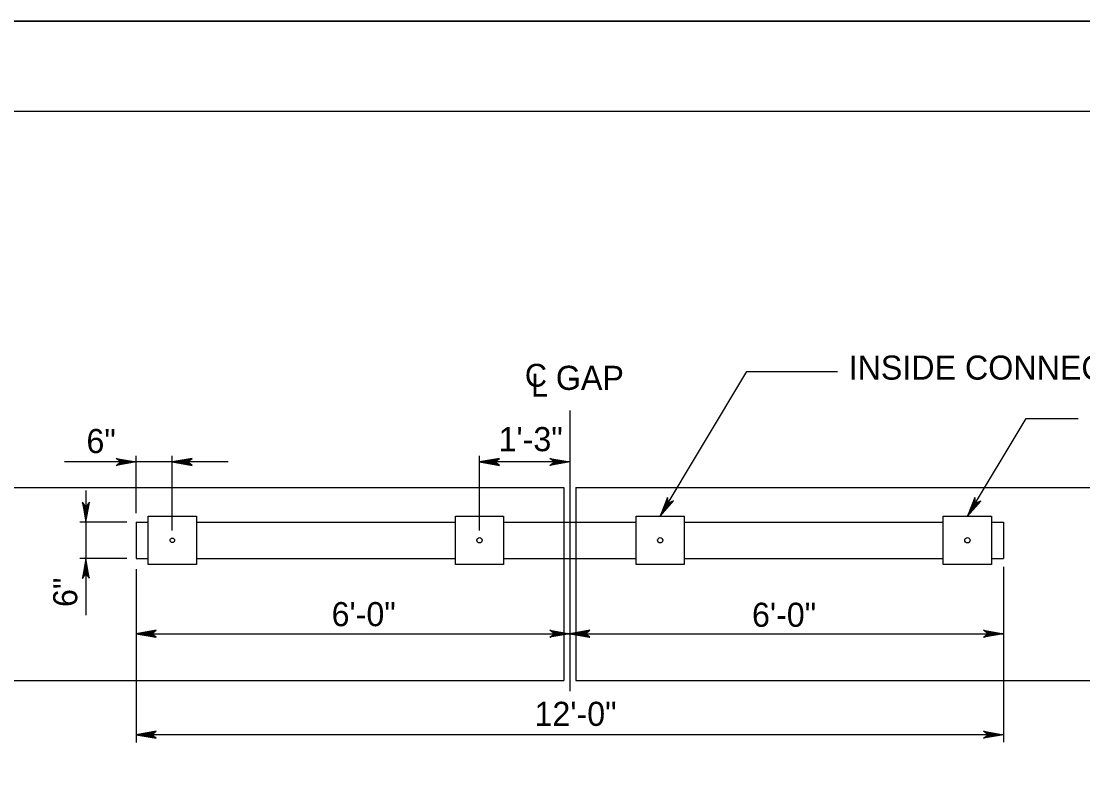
# Model space of a CAD drawing. Extents: x 499881 to 500993, y 499985 to 500645.
# Drawn here: x 500108.7 to 500285, y 500517.7 to 500645 of the extents above; entities that cross this region are included whole.
import ezdxf

# ---------------------------------------------------------------- set-up
doc = ezdxf.new("R2010")
doc.units = 0
for name, color, linetype in [('1', 7, 'Continuous'), ('2', 7, 'Continuous'), ('3', 7, 'Continuous'), ('41', 7, 'Continuous'), ('5', 7, 'Continuous')]:
    doc.layers.add(name, color=color, linetype=linetype)

msp = doc.modelspace()

# ---------------------------------------------------------------- linework, layer by layer
at = {"layer": '1'}
for p, q in [((499944.83, 500645), (500993, 500645)), ((500990, 500630), (500000, 500630))]:
    msp.add_line(p, q, dxfattribs=at)
at = {"layer": '2'}
for points in [[(500127.81, 500571.84), (500124.48, 500571.25), (500125.28, 500571.84), (500124.5, 500572.41), (500127.81, 500571.84), (500127.59, 500571.84), (500124.58, 500571.29), (500125.34, 500571.84), (500124.64, 500572.37), (500127.47, 500571.85), (500127.36, 500571.84), (500124.78, 500571.38), (500125.36, 500571.84), (500124.76, 500572.29), (500127.31, 500571.84), (500127.2, 500571.85), (500124.94, 500571.45), (500125.38, 500571.84), (500124.93, 500572.24), (500126.87, 500571.85), (500126.69, 500571.85), (500125.11, 500571.53), (500125.42, 500571.83), (500125.09, 500572.16), (500126.65, 500571.84), (500126.48, 500571.83), (500125.29, 500571.62), (500125.52, 500571.85), (500125.27, 500572.08), (500126.31, 500571.84), (500126.15, 500571.82), (500125.43, 500571.68), (500125.55, 500571.84), (500125.36, 500572.02), (500126.06, 500571.84), (500125.59, 500571.73), (500125.66, 500571.85), (500125.46, 500571.98), (500125.94, 500571.85), (500125.64, 500571.78), (500125.76, 500571.88), (500125.62, 500571.94), (500125.76, 500571.84), (500125.69, 500571.83)], [(500133.81, 500571.84), (500137.13, 500571.25), (500136.34, 500571.84), (500137.11, 500572.41), (500133.81, 500571.84), (500134.03, 500571.84), (500137.04, 500571.29), (500136.27, 500571.84), (500136.98, 500572.37), (500134.15, 500571.85), (500134.26, 500571.84), (500136.84, 500571.38), (500136.26, 500571.84), (500136.85, 500572.29), (500134.31, 500571.84), (500134.42, 500571.85), (500136.67, 500571.45), (500136.23, 500571.84), (500136.68, 500572.24), (500134.74, 500571.85), (500134.93, 500571.85), (500136.5, 500571.53), (500136.2, 500571.83), (500136.53, 500572.16), (500134.96, 500571.84), (500135.14, 500571.83), (500136.32, 500571.62), (500136.1, 500571.85), (500136.34, 500572.08), (500135.3, 500571.84), (500135.47, 500571.82), (500136.18, 500571.68), (500136.06, 500571.84), (500136.26, 500572.02), (500135.55, 500571.84), (500136.02, 500571.73), (500135.95, 500571.85), (500136.16, 500571.98), (500135.67, 500571.85), (500135.98, 500571.78), (500135.85, 500571.88), (500136, 500571.94), (500135.85, 500571.84), (500135.93, 500571.83)], [(500184.81, 500571.84), (500188.13, 500571.25), (500187.34, 500571.84), (500188.11, 500572.41), (500184.81, 500571.84), (500185.03, 500571.84), (500188.04, 500571.29), (500187.27, 500571.84), (500187.98, 500572.37), (500185.15, 500571.85), (500185.26, 500571.84), (500187.84, 500571.38), (500187.26, 500571.84), (500187.85, 500572.29), (500185.31, 500571.84), (500185.42, 500571.85), (500187.67, 500571.45), (500187.23, 500571.84), (500187.68, 500572.24), (500185.74, 500571.85), (500185.93, 500571.85), (500187.5, 500571.53), (500187.2, 500571.83), (500187.53, 500572.16), (500185.96, 500571.84), (500186.14, 500571.83), (500187.32, 500571.62), (500187.1, 500571.85), (500187.34, 500572.08), (500186.3, 500571.84), (500186.47, 500571.82), (500187.18, 500571.68), (500187.06, 500571.84), (500187.26, 500572.02), (500186.55, 500571.84), (500187.02, 500571.73), (500186.95, 500571.85), (500187.16, 500571.98), (500186.67, 500571.85), (500186.98, 500571.78), (500186.85, 500571.88), (500187, 500571.94), (500186.85, 500571.84), (500186.93, 500571.83)], [(500199.81, 500571.84), (500196.48, 500571.25), (500197.28, 500571.84), (500196.5, 500572.41), (500199.81, 500571.84), (500199.58, 500571.84), (500196.57, 500571.29), (500197.34, 500571.84), (500196.63, 500572.37), (500199.47, 500571.85), (500199.35, 500571.84), (500196.78, 500571.38), (500197.35, 500571.84), (500196.76, 500572.29), (500199.3, 500571.84), (500199.19, 500571.85), (500196.94, 500571.45), (500197.38, 500571.84), (500196.93, 500572.24), (500198.87, 500571.85), (500198.69, 500571.85), (500197.11, 500571.53), (500197.41, 500571.83), (500197.08, 500572.16), (500198.65, 500571.84), (500198.47, 500571.83), (500197.29, 500571.62), (500197.52, 500571.85), (500197.27, 500572.08), (500198.31, 500571.84), (500198.14, 500571.82), (500197.43, 500571.68), (500197.55, 500571.84), (500197.35, 500572.02), (500198.06, 500571.84), (500197.59, 500571.73), (500197.66, 500571.85), (500197.46, 500571.98), (500197.94, 500571.85), (500197.64, 500571.78), (500197.76, 500571.88), (500197.62, 500571.94), (500197.76, 500571.84), (500197.69, 500571.83)], [(500214.81, 500562.83), (500217.04, 500565.36), (500216.12, 500564.99), (500216.04, 500565.95), (500214.81, 500562.83), (500214.92, 500563.02), (500216.95, 500565.3), (500216.09, 500564.94), (500216, 500565.81), (500214.97, 500563.13), (500215.04, 500563.21), (500216.78, 500565.18), (500216.08, 500564.93), (500216, 500565.67), (500215.07, 500563.26), (500215.11, 500563.36), (500216.63, 500565.07), (500216.07, 500564.9), (500215.96, 500565.49), (500215.28, 500563.63), (500215.38, 500563.79), (500216.47, 500564.97), (500216.06, 500564.87), (500215.95, 500565.32), (500215.41, 500563.81), (500215.51, 500563.96), (500216.3, 500564.87), (500215.99, 500564.79), (500215.92, 500565.12), (500215.59, 500564.11), (500215.69, 500564.24), (500216.17, 500564.78), (500215.98, 500564.76), (500215.93, 500565.02), (500215.72, 500564.32), (500216.05, 500564.66), (500215.91, 500564.67), (500215.91, 500564.91), (500215.76, 500564.43), (500215.99, 500564.65), (500215.84, 500564.59), (500215.86, 500564.75), (500215.86, 500564.58), (500215.92, 500564.63)], [(500265.81, 500562.83), (500268.06, 500565.35), (500267.14, 500564.98), (500267.06, 500565.95), (500265.81, 500562.83), (500265.92, 500563.02), (500267.97, 500565.29), (500267.1, 500564.93), (500267.02, 500565.81), (500265.97, 500563.13), (500266.04, 500563.21), (500267.79, 500565.16), (500267.09, 500564.92), (500267.02, 500565.66), (500266.07, 500563.26), (500266.11, 500563.36), (500267.65, 500565.06), (500267.08, 500564.89), (500266.97, 500565.49), (500266.28, 500563.63), (500266.38, 500563.79), (500267.49, 500564.96), (500267.07, 500564.86), (500266.97, 500565.31), (500266.41, 500563.81), (500266.52, 500563.96), (500267.31, 500564.86), (500267, 500564.79), (500266.93, 500565.12), (500266.59, 500564.1), (500266.69, 500564.23), (500267.19, 500564.77), (500266.99, 500564.75), (500266.94, 500565.01), (500266.73, 500564.32), (500267.06, 500564.65), (500266.92, 500564.66), (500266.92, 500564.9), (500266.77, 500564.42), (500267, 500564.64), (500266.85, 500564.59), (500266.87, 500564.74), (500266.88, 500564.57), (500266.93, 500564.63)], [(500119.47, 500561.83), (500120.05, 500565.15), (500119.47, 500564.36), (500118.89, 500565.14), (500119.47, 500561.83), (500119.46, 500562.05), (500120.01, 500565.06), (500119.46, 500564.3), (500118.93, 500565), (500119.45, 500562.17), (500119.47, 500562.28), (500119.92, 500564.86), (500119.46, 500564.28), (500119.01, 500564.88), (500119.47, 500562.33), (500119.45, 500562.44), (500119.86, 500564.7), (500119.47, 500564.26), (500119.06, 500564.71), (500119.45, 500562.76), (500119.45, 500562.95), (500119.77, 500564.53), (500119.47, 500564.22), (500119.14, 500564.55), (500119.47, 500562.98), (500119.48, 500563.16), (500119.68, 500564.35), (500119.45, 500564.12), (500119.22, 500564.37), (500119.47, 500563.32), (500119.48, 500563.49), (500119.62, 500564.2), (500119.46, 500564.09), (500119.28, 500564.28), (500119.47, 500563.58), (500119.58, 500564.04), (500119.45, 500563.98), (500119.32, 500564.18), (500119.45, 500563.7), (500119.53, 500564), (500119.42, 500563.87), (500119.36, 500564.02), (500119.46, 500563.87), (500119.47, 500563.95)], [(500119.47, 500555.83), (500118.88, 500552.51), (500119.47, 500553.3), (500120.04, 500552.52), (500119.47, 500555.83), (500119.47, 500555.61), (500118.92, 500552.6), (500119.47, 500553.36), (500120, 500552.66), (500119.48, 500555.49), (500119.47, 500555.38), (500119.01, 500552.8), (500119.47, 500553.38), (500119.92, 500552.78), (500119.47, 500555.33), (500119.48, 500555.22), (500119.08, 500552.96), (500119.47, 500553.4), (500119.87, 500552.96), (500119.48, 500554.9), (500119.48, 500554.71), (500119.16, 500553.13), (500119.46, 500553.44), (500119.79, 500553.11), (500119.47, 500554.68), (500119.46, 500554.5), (500119.25, 500553.31), (500119.48, 500553.54), (500119.71, 500553.29), (500119.47, 500554.34), (500119.45, 500554.17), (500119.31, 500553.46), (500119.47, 500553.57), (500119.65, 500553.38), (500119.47, 500554.08), (500119.36, 500553.62), (500119.48, 500553.68), (500119.61, 500553.48), (500119.48, 500553.97), (500119.41, 500553.66), (500119.51, 500553.79), (500119.57, 500553.64), (500119.47, 500553.79), (500119.46, 500553.71)], [(500127.81, 500543.31), (500131.13, 500542.72), (500130.34, 500543.31), (500131.11, 500543.89), (500127.81, 500543.31), (500128.03, 500543.32), (500131.04, 500542.77), (500130.27, 500543.32), (500130.98, 500543.85), (500128.15, 500543.33), (500128.26, 500543.31), (500130.84, 500542.85), (500130.26, 500543.32), (500130.85, 500543.77), (500128.31, 500543.31), (500128.42, 500543.33), (500130.67, 500542.92), (500130.23, 500543.31), (500130.68, 500543.72), (500128.74, 500543.33), (500128.93, 500543.33), (500130.5, 500543.01), (500130.2, 500543.3), (500130.53, 500543.63), (500128.96, 500543.31), (500129.14, 500543.3), (500130.32, 500543.1), (500130.1, 500543.33), (500130.34, 500543.56), (500129.3, 500543.31), (500129.47, 500543.3), (500130.18, 500543.16), (500130.06, 500543.32), (500130.26, 500543.5), (500129.55, 500543.31), (500130.02, 500543.2), (500129.95, 500543.33), (500130.16, 500543.46), (500129.67, 500543.33), (500129.98, 500543.25), (500129.85, 500543.35), (500130, 500543.41), (500129.85, 500543.32), (500129.93, 500543.3)], [(500199.8, 500543.31), (500196.47, 500542.72), (500197.27, 500543.31), (500196.49, 500543.89), (500199.8, 500543.31), (500199.58, 500543.32), (500196.57, 500542.77), (500197.33, 500543.32), (500196.62, 500543.85), (500199.46, 500543.33), (500199.35, 500543.31), (500196.77, 500542.85), (500197.35, 500543.32), (500196.75, 500543.77), (500199.3, 500543.31), (500199.18, 500543.33), (500196.93, 500542.92), (500197.37, 500543.31), (500196.92, 500543.72), (500198.86, 500543.33), (500198.68, 500543.33), (500197.1, 500543.01), (500197.4, 500543.3), (500197.07, 500543.63), (500198.64, 500543.31), (500198.46, 500543.3), (500197.28, 500543.1), (500197.51, 500543.33), (500197.26, 500543.56), (500198.3, 500543.31), (500198.13, 500543.3), (500197.42, 500543.16), (500197.54, 500543.32), (500197.35, 500543.5), (500198.05, 500543.31), (500197.58, 500543.2), (500197.65, 500543.33), (500197.45, 500543.46), (500197.93, 500543.33), (500197.63, 500543.25), (500197.75, 500543.35), (500197.61, 500543.41), (500197.75, 500543.32), (500197.68, 500543.3)], [(500199.81, 500543.31), (500203.13, 500542.72), (500202.34, 500543.31), (500203.11, 500543.89), (500199.81, 500543.31), (500200.03, 500543.32), (500203.04, 500542.77), (500202.27, 500543.32), (500202.98, 500543.85), (500200.15, 500543.33), (500200.26, 500543.31), (500202.84, 500542.85), (500202.26, 500543.32), (500202.85, 500543.77), (500200.31, 500543.31), (500200.42, 500543.33), (500202.67, 500542.92), (500202.23, 500543.31), (500202.68, 500543.72), (500200.74, 500543.33), (500200.93, 500543.33), (500202.5, 500543.01), (500202.2, 500543.3), (500202.53, 500543.63), (500200.96, 500543.31), (500201.14, 500543.3), (500202.32, 500543.1), (500202.1, 500543.33), (500202.34, 500543.56), (500201.3, 500543.31), (500201.47, 500543.3), (500202.18, 500543.16), (500202.06, 500543.32), (500202.26, 500543.5), (500201.55, 500543.31), (500202.02, 500543.2), (500201.95, 500543.33), (500202.16, 500543.46), (500201.67, 500543.33), (500201.98, 500543.25), (500201.85, 500543.35), (500202, 500543.41), (500201.85, 500543.32), (500201.93, 500543.3)], [(500271.81, 500543.31), (500268.48, 500542.72), (500269.28, 500543.31), (500268.5, 500543.89), (500271.81, 500543.31), (500271.59, 500543.32), (500268.58, 500542.77), (500269.34, 500543.32), (500268.63, 500543.85), (500271.47, 500543.33), (500271.36, 500543.31), (500268.78, 500542.85), (500269.36, 500543.32), (500268.76, 500543.77), (500271.3, 500543.31), (500271.19, 500543.33), (500268.94, 500542.92), (500269.38, 500543.31), (500268.93, 500543.72), (500270.87, 500543.33), (500270.69, 500543.33), (500269.11, 500543.01), (500269.41, 500543.3), (500269.08, 500543.63), (500270.65, 500543.31), (500270.47, 500543.3), (500269.29, 500543.1), (500269.52, 500543.33), (500269.27, 500543.56), (500270.31, 500543.31), (500270.14, 500543.3), (500269.43, 500543.16), (500269.55, 500543.32), (500269.35, 500543.5), (500270.06, 500543.31), (500269.59, 500543.2), (500269.66, 500543.33), (500269.46, 500543.46), (500269.94, 500543.33), (500269.64, 500543.25), (500269.76, 500543.35), (500269.62, 500543.41), (500269.76, 500543.32), (500269.69, 500543.3)], [(500127.81, 500526.56), (500131.13, 500525.97), (500130.34, 500526.56), (500131.11, 500527.14), (500127.81, 500526.56), (500128.03, 500526.56), (500131.04, 500526.01), (500130.27, 500526.56), (500130.98, 500527.09), (500128.15, 500526.57), (500128.26, 500526.56), (500130.84, 500526.1), (500130.26, 500526.56), (500130.85, 500527.01), (500128.31, 500526.56), (500128.42, 500526.57), (500130.67, 500526.17), (500130.23, 500526.56), (500130.68, 500526.96), (500128.74, 500526.57), (500128.93, 500526.57), (500130.5, 500526.25), (500130.2, 500526.55), (500130.53, 500526.88), (500128.96, 500526.56), (500129.14, 500526.55), (500130.32, 500526.34), (500130.1, 500526.57), (500130.34, 500526.8), (500129.3, 500526.56), (500129.47, 500526.54), (500130.18, 500526.4), (500130.06, 500526.56), (500130.26, 500526.74), (500129.55, 500526.56), (500130.02, 500526.45), (500129.95, 500526.57), (500130.16, 500526.7), (500129.67, 500526.57), (500129.98, 500526.5), (500129.85, 500526.6), (500130, 500526.66), (500129.85, 500526.56), (500129.93, 500526.55)], [(500271.81, 500526.56), (500268.48, 500525.97), (500269.28, 500526.56), (500268.5, 500527.14), (500271.81, 500526.56), (500271.58, 500526.56), (500268.57, 500526.01), (500269.34, 500526.56), (500268.63, 500527.09), (500271.46, 500526.57), (500271.35, 500526.56), (500268.78, 500526.1), (500269.35, 500526.56), (500268.76, 500527.01), (500271.3, 500526.56), (500271.19, 500526.57), (500268.94, 500526.17), (500269.38, 500526.56), (500268.93, 500526.96), (500270.87, 500526.57), (500270.68, 500526.57), (500269.11, 500526.25), (500269.41, 500526.55), (500269.08, 500526.88), (500270.65, 500526.56), (500270.47, 500526.55), (500269.29, 500526.34), (500269.52, 500526.57), (500269.27, 500526.8), (500270.31, 500526.56), (500270.14, 500526.54), (500269.43, 500526.4), (500269.55, 500526.56), (500269.35, 500526.74), (500270.06, 500526.56), (500269.59, 500526.45), (500269.66, 500526.57), (500269.46, 500526.7), (500269.94, 500526.57), (500269.63, 500526.5), (500269.76, 500526.6), (500269.62, 500526.66), (500269.76, 500526.56), (500269.69, 500526.55)]]:
    msp.add_lwpolyline(points, dxfattribs=at)
at = {"layer": '3'}
for p, q in [((500214.81, 500562.83), (500229.22, 500586.85)), ((500229.22, 500586.85), (500244.25, 500586.85)), ((500199.81, 500580.38), (500199.81, 500533.81)), ((500265.81, 500562.83), (500275.54, 500579.06)), ((500275.54, 500579.06), (500284.21, 500579.06)), ((500127.81, 500563.35), (500127.81, 500572.85)), ((500133.81, 500560.43), (500133.81, 500572.85)), ((500184.81, 500560.43), (500184.81, 500572.85)), ((500127.81, 500571.84), (500115.91, 500571.84)), ((500133.81, 500571.84), (500127.83, 500571.84)), ((500143.09, 500571.84), (500133.81, 500571.84)), ((500199.81, 500571.84), (500184.81, 500571.84)), ((500055.81, 500567.57), (500198.81, 500567.57)), ((500198.81, 500567.57), (500198.81, 500561.82)), ((500200.81, 500567.57), (500343.81, 500567.57)), ((500200.81, 500567.57), (500200.81, 500561.82)), ((500119.47, 500567.1), (500119.47, 500561.83)), ((500126.28, 500561.83), (500118.45, 500561.83)), ((500119.47, 500561.83), (500119.47, 500555.83)), ((500127.81, 500561.83), (500127.81, 500555.83)), ((500127.81, 500561.83), (500129.81, 500561.83)), ((500137.81, 500561.83), (500180.81, 500561.83)), ((500188.81, 500561.83), (500210.81, 500561.83)), ((500198.81, 500561.8), (500198.81, 500555.86)), ((500200.81, 500561.81), (500200.81, 500555.85)), ((500218.81, 500561.83), (500261.81, 500561.83)), ((500269.81, 500561.83), (500271.81, 500561.83)), ((500271.81, 500561.83), (500271.81, 500555.83)), ((500126.24, 500555.83), (500118.45, 500555.83)), ((500119.47, 500555.83), (500119.47, 500546.41)), ((500127.81, 500555.83), (500129.81, 500555.83)), ((500137.81, 500555.83), (500180.81, 500555.83)), ((500188.81, 500555.83), (500210.81, 500555.83)), ((500198.81, 500555.84), (500198.81, 500535.58)), ((500200.81, 500555.84), (500200.81, 500535.58)), ((500218.81, 500555.83), (500261.81, 500555.83)), ((500269.81, 500555.83), (500271.81, 500555.83)), ((500127.81, 500554.06), (500127.81, 500525.27)), ((500271.81, 500554.4), (500271.81, 500525.31)), ((500127.81, 500543.31), (500199.81, 500543.31)), ((500199.81, 500543.31), (500271.81, 500543.31)), ((500055.81, 500535.58), (500198.81, 500535.58)), ((500200.81, 500535.58), (500343.81, 500535.58)), ((500271.81, 500526.56), (500127.81, 500526.56))]:
    msp.add_line(p, q, dxfattribs=at)
for points in [[(500129.81, 500562.83), (500137.81, 500562.83), (500137.81, 500554.83), (500129.81, 500554.83)], [(500180.81, 500562.83), (500188.81, 500562.83), (500188.81, 500554.83), (500180.81, 500554.83)], [(500210.81, 500562.83), (500218.81, 500562.83), (500218.81, 500554.83), (500210.81, 500554.83)], [(500261.81, 500562.83), (500269.81, 500562.83), (500269.81, 500554.83), (500261.81, 500554.83)]]:
    msp.add_lwpolyline(points, close=True, dxfattribs=at)
for centre, radius in [((500133.81, 500558.83), 0.375), ((500184.81, 500558.83), 0.437), ((500214.81, 500558.83), 0.437), ((500265.81, 500558.83), 0.437)]:
    msp.add_circle(centre, radius, dxfattribs=at)
at = {"layer": '41'}
msp.add_lwpolyline([(499944.83, 499985), (500993, 499985), (500993, 500645), (499944.83, 500645)], close=True, dxfattribs=at)

# ---------------------------------------------------------------- texts
at = {"layer": '3'}
for s, p in [('INSIDE CONNECTION', (500246.09, 500585.5)), ('GAP', (500197.49, 500583.8)), ('6"', (500119.56, 500573.31)), ('1\'-3"', (500187.98, 500573.62)), ('6\'-0"', (500160.26, 500544.57)), ('6\'-0"', (500230.05, 500544.47)), ('12\'-0"', (500193.94, 500528.02))]:
    msp.add_text(s, height=4, dxfattribs=at).set_placement(p)
msp.add_text('6"', height=4, rotation=90, dxfattribs=at).set_placement((500118.04, 500547.76))
at = {"layer": '5'}
for s, p in [('C', (500192.35, 500584.32)), ('L', (500193.37, 500582.67))]:
    msp.add_text(s, height=3.8, dxfattribs=at).set_placement(p)

doc.saveas('drawing.dxf')
